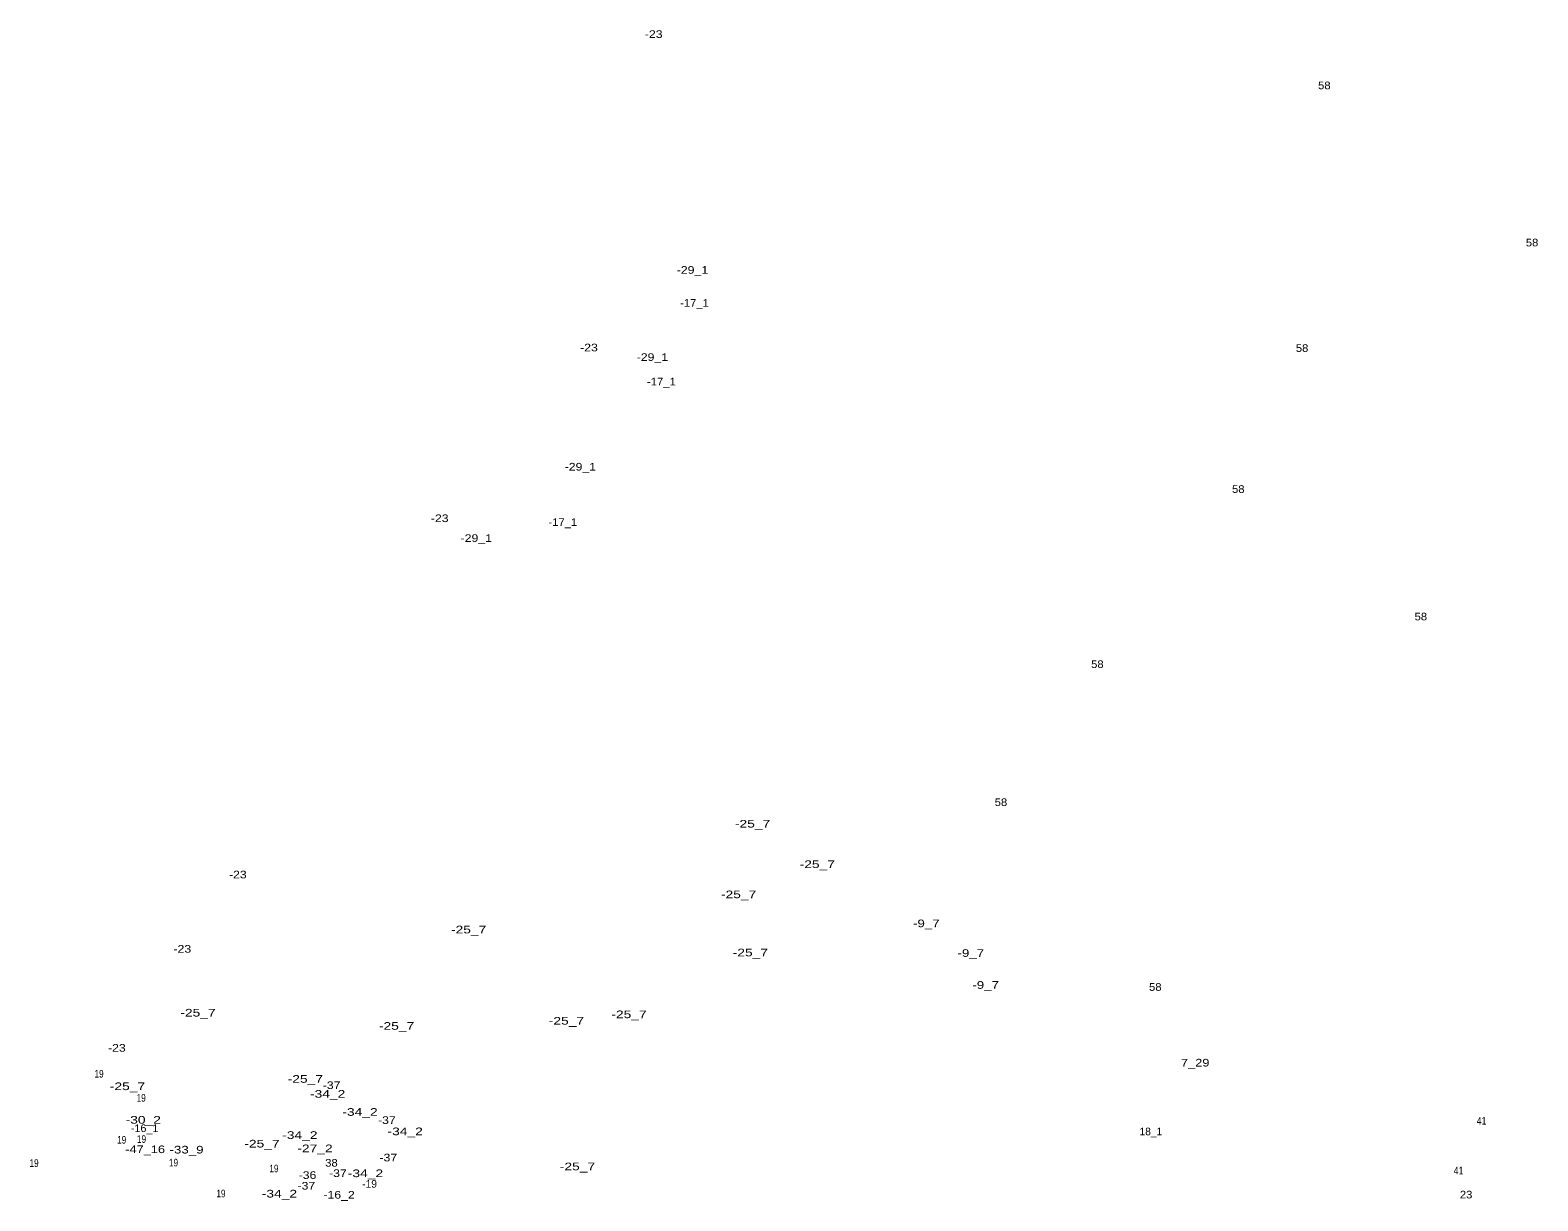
# Model space of a CAD drawing. Extents: x -663705 to -661666, y -1002081 to -999269.
# Drawn here: x -663705 to -662917, y -1000585 to -999973 of the extents above; entities that cross this region are included whole.
import ezdxf
from ezdxf.enums import TextEntityAlignment as Align

# ---------------------------------------------------------------- set-up
doc = ezdxf.new("R2010")
doc.units = 0
doc.header["$LTSCALE"] = 1.6
doc.layers.add('24', color=7, linetype='Continuous')

msp = doc.modelspace()

# ---------------------------------------------------------------- texts
at = {"layer": '24'}
for s, width, p in [('-23', 1.2, (-663378.98, -999976.77)), ('58', 1.1, (-663028.38, -1000003.59)), ('58', 1.1, (-662919.77, -1000085.74)), ('-29_1', 1.2, (-663358.711, -1000100.05)), ('-17_1', 1.1, (-663357.671, -1000117.26)), ('-23', 1.2, (-663412.82, -1000140.62)), ('-29_1', 1.2, (-663379.66, -1000145.6)), ('58', 1.1, (-663040.01, -1000140.9)), ('-17_1', 1.1, (-663374.971, -1000158.42)), ('-29_1', 1.2, (-663417.341, -1000202.91)), ('58', 1.1, (-663073.36, -1000214.59)), ('-23', 1.2, (-663490.86, -1000229.85)), ('-17_1', 1.1, (-663426.49, -1000231.88)), ('-29_1', 1.2, (-663471.74, -1000240.22)), ('58', 1.1, (-662977.929, -1000281.23)), ('58', 1.1, (-663147.03, -1000306.13)), ('58', 1.1, (-663197.429, -1000378.28)), ('-25_7', 1.35, (-663327.3, -1000389.54)), ('-25_7', 1.35, (-663293.46, -1000410.69)), ('-23', 1.2, (-663596.4, -1000416.1)), ('-25_7', 1.35, (-663334.6, -1000426.46)), ('-25_7', 1.35, (-663475.74, -1000444.85)), ('-9_7', 1.3, (-663236.461, -1000441.61)), ('-23', 1.2, (-663625.42, -1000454.94)), ('-25_7', 1.35, (-663328.45, -1000456.85)), ('-9_7', 1.3, (-663213.191, -1000457.12)), ('-9_7', 1.3, (-663205.441, -1000473.8)), ('58', 1.1, (-663116.74, -1000474.86)), ('-25_7', 1.35, (-663617.23, -1000488.31)), ('-25_7', 1.35, (-663424.61, -1000492.54)), ('-25_7', 1.35, (-663391.89, -1000489.16)), ('-25_7', 1.35, (-663513.42, -1000495.23)), ('-23', 1.2, (-663659.64, -1000506.68)), ('7_29', 1.25, (-663095.89, -1000514.43)), ('19', 0.8, (-663668.941, -1000520.22)), ('-25_7', 1.35, (-663561.1, -1000522.92)), ('-25_7', 1.35, (-663654.1, -1000526.77)), ('19', 0.8, (-663646.931, -1000532.81)), ('-34_2', 1.35, (-663549.45, -1000530.74)), ('-37', 1.2, (-663547.38, -1000526.21)), ('-34_2', 1.35, (-663532.53, -1000540.2)), ('-30_2', 1.35, (-663645.84, -1000544.31)), ('-16_1', 1.05, (-663645.13, -1000548.66)), ('-37', 1.2, (-663518.5, -1000544.44)), ('41', 0.85, (-662946.169, -1000544.81)), ('19', 0.8, (-663657.12, -1000554.73)), ('19', 0.8, (-663646.74, -1000554.35)), ('-34_2', 1.35, (-663563.98, -1000552.27)), ('-34_2', 1.35, (-663508.92, -1000550.33)), ('-47_16', 1.25, (-663644.87, -1000559.7)), ('-33_9', 1.3, (-663623.22, -1000559.9)), ('-25_7', 1.35, (-663583.78, -1000556.77)), ('-27_2', 1.35, (-663556.06, -1000559.23)), ('-37', 1.2, (-663517.721, -1000564.03)), ('19', 0.8, (-663702.921, -1000566.91)), ('19', 0.8, (-663630.02, -1000566.65)), ('19', 0.8, (-663577.53, -1000569.73)), ('38', 1.1, (-663547.459, -1000566.75)), ('-37', 1.2, (-663544.091, -1000572.18)), ('-34_2', 1.35, (-663529.67, -1000572.25)), ('-25_7', 1.35, (-663418.84, -1000568.69)), ('41', 0.85, (-662958.189, -1000570.8)), ('-37', 1.2, (-663560.571, -1000578.77)), ('-36', 1.2, (-663559.98, -1000573.19)), ('19', 0.8, (-663605.221, -1000582.81)), ('-34_2', 1.35, (-663574.65, -1000582.9)), ('-16_2', 1.2, (-663543.471, -1000583.49)), ('23', 1.1, (-662954.26, -1000583.38))]:
    msp.add_text(s, height=4, dxfattribs=dict(at, width=width)).set_placement(p, align=Align.CENTER)
for s, p in [('18_1', (-663119.06, -1000550.37)), ('-19', (-663527.52, -1000577.77))]:
    msp.add_text(s, height=4, dxfattribs=at).set_placement(p, align=Align.CENTER)

doc.saveas('drawing.dxf')
